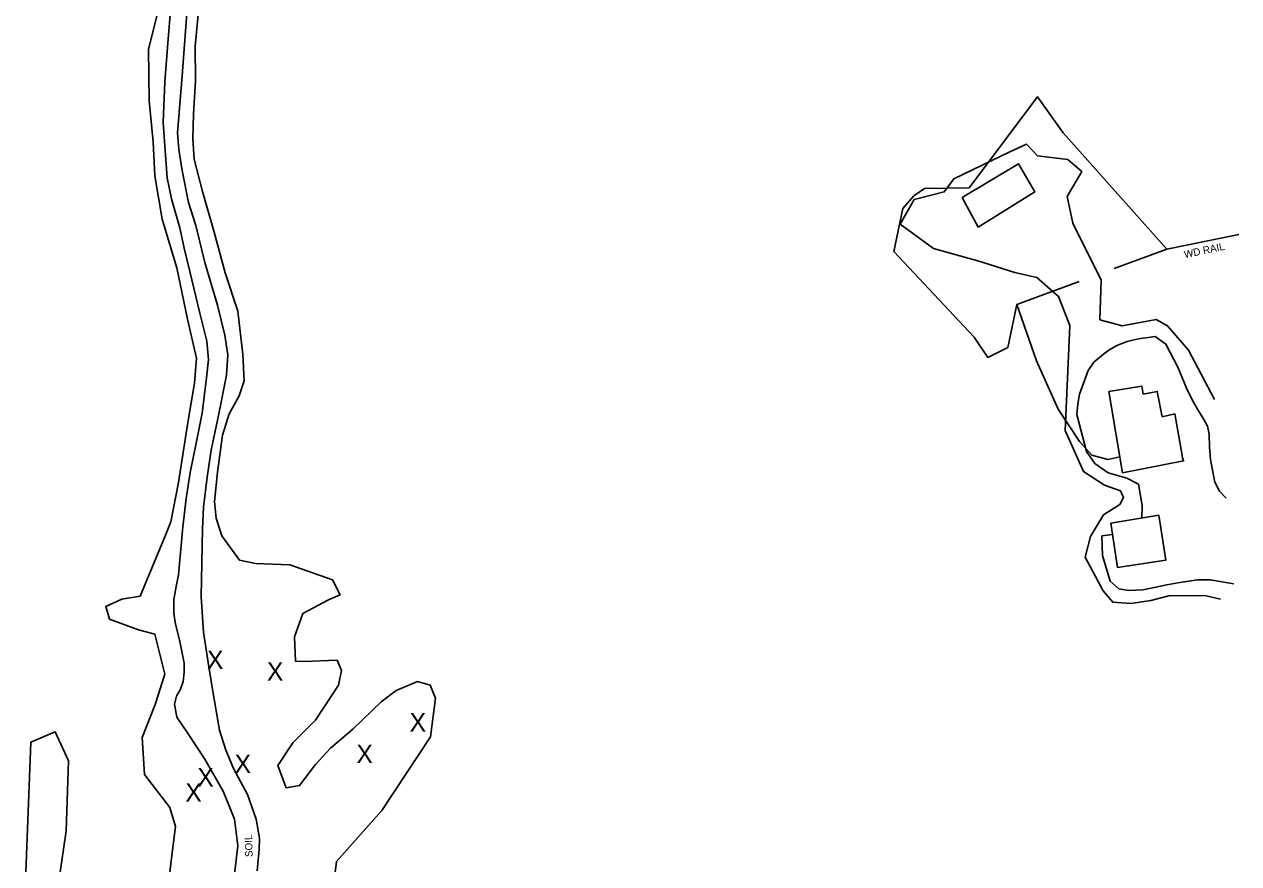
# Model space of a CAD drawing. Extents: x 2030130 to 2036320, y 723205 to 762423.
# Drawn here: x 2031733 to 2032390, y 750602 to 751056 of the extents above; entities that cross this region are included whole.
import ezdxf

# ---------------------------------------------------------------- set-up
doc = ezdxf.new("R2010")
doc.units = 0
for name, color, linetype in [('Draft_Station Labels Major', 7, 'Continuous'), ('Draft_Station Tics Major', 7, 'Continuous'), ('Exist Terrain Model Ground Surface', 7, 'Continuous'), ('Old_Level_23', 7, 'Continuous'), ('Old_Level_26', 7, 'Continuous')]:
    doc.layers.add(name, color=color, linetype=linetype)

msp = doc.modelspace()

# ---------------------------------------------------------------- linework, layer by layer
at = {"layer": 'Draft_Station Labels Major'}
for points in [[(2031822.23, 751081.93), (2031818.25, 751028.53), (2031815.64, 750997.62), (2031816.32, 750988.66), (2031818.2, 750977.2), (2031821.6, 750959.87), (2031825.61, 750947.38), (2031830.39, 750927.47), (2031837.33, 750904.3), (2031841.39, 750888.05), (2031842.87, 750877.45), (2031842.13, 750866.44), (2031838.05, 750845.46), (2031833.95, 750825.73), (2031831.81, 750811.13), (2031829.79, 750794.99), (2031829.26, 750783.31)], [(2031818.59, 750784.33), (2031820.33, 750799.59), (2031822.48, 750813.7), (2031825.75, 750829.66), (2031829.03, 750845.82), (2031831.3, 750864.95), (2031832.53, 750874.9), (2031831.54, 750884.82), (2031827.79, 750900.02), (2031822.4, 750922.53), (2031819.25, 750935.13), (2031817, 750946.1), (2031812.37, 750961.96), (2031810.01, 750973.32), (2031809.18, 750985.56), (2031808, 751003.2), (2031808.79, 751025.21), (2031810.37, 751046.17), (2031812.15, 751066.06)], [(2032337.74, 750789.03), (2032337.96, 750795.87), (2032336.08, 750807.42), (2032329.68, 750810.71), (2032319.52, 750813.58), (2032312.42, 750818.6), (2032307.9, 750825.01), (2032302.64, 750845.19), (2032303.15, 750850.89), (2032304.05, 750856.11), (2032308.81, 750868.99), (2032311.84, 750873.46), (2032317, 750877.77), (2032319.96, 750879.93), (2032324.36, 750882.49), (2032329.83, 750884.68), (2032335.99, 750886.01), (2032344.94, 750887.37), (2032350.88, 750883.2), (2032357.39, 750870.74), (2032362.06, 750859.33), (2032365.13, 750853.09), (2032367.89, 750847.92), (2032371.34, 750842.37), (2032373.31, 750838.83), (2032374.33, 750834.4), (2032374.41, 750827.65), (2032374.98, 750820.72), (2032375.29, 750818.79), (2032377.34, 750808.4), (2032379.91, 750803.61), (2032383.43, 750799.9)], [(2031845.62, 750588.62), (2031848.29, 750611.49), (2031846.63, 750626.08), (2031840.41, 750641.19), (2031830.39, 750658.46), (2031821.08, 750672.74), (2031815.35, 750681.18), (2031814.08, 750688.22), (2031815.09, 750692.59), (2031817.26, 750696.4), (2031818.75, 750700.48), (2031819.35, 750705.52), (2031819.37, 750710.56), (2031816.77, 750723.1), (2031814.52, 750731.68), (2031813.76, 750737.38), (2031813.75, 750745.02), (2031814.9, 750752.01), (2031816.17, 750758.32), (2031817.42, 750772.27), (2031818.59, 750784.33)], [(2031829.26, 750783.31), (2031828.44, 750746.34), (2031829.78, 750727.29), (2031832.24, 750710.78), (2031834.58, 750696.3), (2031838.38, 750674.29), (2031841.93, 750663.4), (2031846.04, 750653.4), (2031853.6, 750639.28), (2031858.24, 750626), (2031860.03, 750615.76), (2031859.93, 750609.76), (2031858.74, 750598.13)], [(2032322, 750780.16), (2032316.18, 750779.4), (2032316.5, 750768.7), (2032320.62, 750754.96), (2032325.4, 750750.68), (2032330.71, 750749.88), (2032338.42, 750750.26), (2032345.45, 750751.6), (2032351.31, 750752.93), (2032357.28, 750753.96), (2032367.96, 750755.64), (2032374.81, 750755.62), (2032387.56, 750753.47)]]:
    msp.add_lwpolyline(points, dxfattribs=at)
at = {"layer": 'Draft_Station Tics Major'}
for points in [[(2031806.95, 751071.08), (2031800.03, 751042.91), (2031800.37, 751014.95), (2031802.59, 750992.69), (2031803.41, 750974.32), (2031807.44, 750950.93), (2031815.25, 750924.49), (2031821.1, 750896.73), (2031825.96, 750875.64), (2031824.81, 750862.1), (2031821.26, 750840.72), (2031816.21, 750808.22)], [(2031839.75, 750779.33), (2031836.61, 750789.07), (2031835.72, 750797.92), (2031837.28, 750813.93), (2031840.12, 750833.86), (2031843.66, 750845.52), (2031848.99, 750855.24), (2031851.84, 750863.35), (2031851.01, 750877.59), (2031848.36, 750901), (2031841.54, 750921.86), (2031835.49, 750943.85), (2031829.18, 750965.9), (2031824.77, 750983.44), (2031823.92, 750994.43), (2031824.26, 751007.77), (2031825.35, 751026.04), (2031825.28, 751044.6), (2031827.02, 751063.4)], [(2032377.2, 750853.21), (2032363.12, 750879.95), (2032351.73, 750893.17), (2032345.5, 750896.58), (2032327.15, 750893.06), (2032315.11, 750896.4), (2032315.81, 750917.89), (2032300.53, 750948.68), (2032297.45, 750963.16), (2032305.41, 750976.62), (2032297.78, 750983.11), (2032281.37, 750985.23), (2032275.29, 750991.49), (2032266.36, 750987.25), (2032236, 750972.63), (2032230.86, 750965.6), (2032214.61, 750961.57), (2032207.03, 750948.12), (2032225, 750934.98), (2032249.09, 750928.31), (2032269.11, 750921.97), (2032280.95, 750919.21), (2032292.69, 750909.09), (2032298.88, 750893.3), (2032297.83, 750868.7), (2032296.29, 750836.54), (2032306.3, 750814.25), (2032317.56, 750806.8), (2032326.31, 750803.81), (2032327.9, 750800.15), (2032325.82, 750796.45), (2032316.98, 750790.72), (2032309.96, 750779.02), (2032307.15, 750767.89), (2032316.79, 750749.63), (2032322.09, 750743.5), (2032331.89, 750742.7), (2032342.71, 750744.38), (2032352.36, 750747.02), (2032366.68, 750747.19), (2032372.69, 750746.88), (2032380.46, 750745.04)], [(2031816.21, 750808.22), (2031812.01, 750787.02), (2031808.79, 750778.95)], [(2031808.79, 750778.95), (2031795.51, 750746.81), (2031785.46, 750745.11), (2031776.81, 750741.11), (2031778.84, 750734.37), (2031794.61, 750728.59), (2031803.36, 750726.2), (2031808.9, 750704.6), (2031803.52, 750688.06), (2031796.62, 750670.15), (2031797.87, 750650.22), (2031811.46, 750632.32), (2031814.51, 750622.1), (2031812.26, 750603.48), (2031809.68, 750581.37)], [(2031899.66, 750585.19), (2031901.72, 750603.04), (2031926.3, 750630.69), (2031952.64, 750670.57), (2031955.43, 750691.52), (2031952.43, 750698.65), (2031945.62, 750700.48), (2031934.07, 750695.67), (2031926.03, 750689.55), (2031910.56, 750674.8), (2031898.51, 750664.37), (2031890.31, 750655.54), (2031881.77, 750644.18), (2031874.43, 750642.91), (2031869.99, 750655.05), (2031878.14, 750667.37), (2031890.35, 750679.55), (2031902.86, 750698.51), (2031904.49, 750706.47), (2031902.08, 750712.05), (2031884.28, 750711.41), (2031879.63, 750711.53), (2031879.05, 750724.69), (2031883.52, 750737.34), (2031897.35, 750744.71), (2031903.7, 750747.51), (2031899.52, 750755.58), (2031876.55, 750763.77), (2031857.95, 750764.47), (2031849.21, 750766.28), (2031839.75, 750779.33)], [(2031750.38, 750584.97), (2031755.49, 750619.7), (2031756.68, 750657.67), (2031749.49, 750673.25), (2031736.21, 750667.64), (2031732.73, 750573.68)]]:
    msp.add_lwpolyline(points, dxfattribs=at)
at = {"layer": 'Exist Terrain Model Ground Surface'}
for points in [[(2032325.95, 750822.21), (2032319.34, 750820.71), (2032310.82, 750823.11), (2032303.98, 750830.46), (2032292.58, 750848.06), (2032280.78, 750874.24), (2032270.19, 750904.68), (2032265.17, 750881.38), (2032254.43, 750876.04), (2032247.07, 750886.94), (2032203.59, 750933.37), (2032208.41, 750956.67), (2032214.4, 750963.59), (2032220.14, 750967.52), (2032244.34, 750967.91), (2032281.35, 751017.16), (2032295.28, 750997.66), (2032351.31, 750934.6), (2032390.26, 750942.6)], [(2032322.79, 750924.09), (2032351.31, 750934.6)], [(2032270.19, 750904.68), (2032303.84, 750917.1)]]:
    msp.add_lwpolyline(points, dxfattribs=at)
for points in [[(2032240.58, 750962.54), (2032271.11, 750980.91), (2032279.81, 750965.64), (2032249.28, 750946.59)], [(2032319.87, 750857.61), (2032337.82, 750860.45), (2032338.55, 750856.2), (2032346.18, 750857.65), (2032348.83, 750843.91), (2032355.68, 750845.45), (2032359.42, 750824.02), (2032359.84, 750821.7), (2032360.44, 750819.97), (2032327.43, 750813.57)], [(2032321.09, 750786.21), (2032346.96, 750790.59), (2032350.84, 750766.26), (2032324.67, 750762.26)]]:
    msp.add_lwpolyline(points, close=True, dxfattribs=at)

# ---------------------------------------------------------------- texts
at = {"layer": 'Draft_Station Tics Major'}
for p in [(2031831.66, 750707.29), (2031864.08, 750700.98), (2031941.35, 750673.44), (2031912.55, 750656.37), (2031846.6, 750650.96), (2031826.38, 750643.7), (2031819.91, 750635.48)]:
    msp.add_text('X', height=10, dxfattribs=at).set_placement(p)
at = {"layer": 'Old_Level_23'}
msp.add_text('SOIL', height=4, rotation=91.41523, dxfattribs=at).set_placement((2031856.36, 750605.57))
at = {"layer": 'Old_Level_26'}
msp.add_text('WD RAIL', height=4, rotation=11.88145, dxfattribs=at).set_placement((2032361.15, 750929.75))

doc.saveas('drawing.dxf')
